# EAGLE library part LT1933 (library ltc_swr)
LT1933 - 600mA, 500kHz Step-Down Switching Regulator in SOT-23 Wide Input Range: 3.6V to 36V 5V at 600mA from 16V to 36V Input 3.3V at 600mA from 12V to 36V Input 5V at 500mA from 6.3V to 36V Input 3.3V at 500mA from 4.5V to 36V Input Fixed Frequency 500kHz Operation Uses Tiny Capacitors and Inductors Soft-Start Internally Compensated Low Shutdown Current: <2&micro;A Output Adjustable Down to 1.25V Low Profile (1mm) SOT-23 (ThinSOT&trade;) and (2mm x 3mm x 0.75mm) 6-Pin DFN Packages
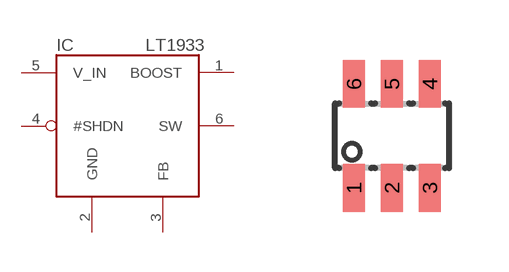
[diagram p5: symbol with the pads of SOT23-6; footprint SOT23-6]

Designator prefix IC

## LT1933ES6  [SOT23-6]
1  BOOST  pas
2  GND  pwr
3  FB  pas
4  #SHDN  pas
5  V_IN  pas
6  SW  pas

## Footprint SOT23-6 (pad centres in mm)
smd 0.55 x 1.2: 1 -0.95,-1.3; 2 0,-1.3; 3 0.95,-1.3; 4 0.95,1.3; 5 0,1.3; 6 -0.95,1.3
